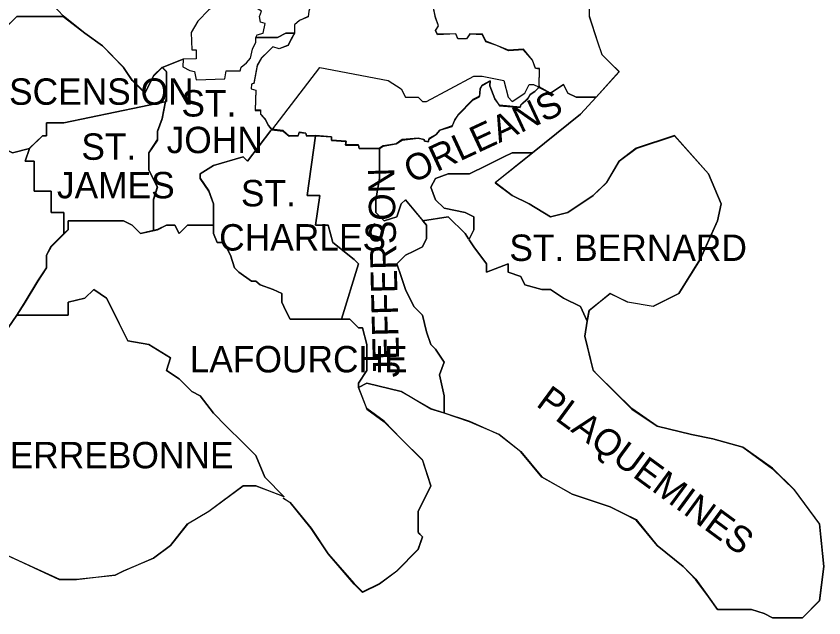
# Model space of a CAD drawing. Extents: x 0.19 to 2.82, y 0.04 to 1.79.
# Drawn here: x 2.4368 to 2.5798, y 1.4148 to 1.5215 of the extents above; entities that cross this region are included whole.
import ezdxf

# ---------------------------------------------------------------- set-up
doc = ezdxf.new("R2010")
doc.units = 0
for name, color, linetype in [('Dist02', 7, 'Continuous'), ('Dist61', 7, 'Continuous'), ('Dist62', 7, 'Continuous'), ('Standard Info', 7, 'Continuous')]:
    doc.layers.add(name, color=color, linetype=linetype)

msp = doc.modelspace()

# ---------------------------------------------------------------- linework, layer by layer
at = {"layer": 'Dist02'}
for points in [[(2.5294, 1.50908), (2.52924, 1.50867), (2.52865, 1.50808), (2.52782, 1.50758), (2.5274, 1.50692), (2.52615, 1.50575), (2.52607, 1.50533), (2.5224, 1.50567), (2.52157, 1.50683), (2.52065, 1.50908), (2.52074, 1.51), (2.51932, 1.50925), (2.51899, 1.50858), (2.51882, 1.50725), (2.51765, 1.50667), (2.51507, 1.504), (2.51449, 1.50308), (2.51399, 1.502), (2.51182, 1.50125), (2.51115, 1.5005), (2.5099, 1.49975), (2.50982, 1.49925), (2.50915, 1.49933), (2.50899, 1.49958), (2.50799, 1.49983), (2.50515, 1.49958), (2.50407, 1.49883), (2.50182, 1.4985), (2.50115, 1.49808)], [(2.53949, 1.50708), (2.53599, 1.50708), (2.53449, 1.50783), (2.53374, 1.50933), (2.5314, 1.50783), (2.5294, 1.50892)], [(2.53674, 1.50408), (2.53949, 1.50708)], [(2.52824, 1.49725), (2.53674, 1.50408)], [(2.4819, 1.50117), (2.47774, 1.49575), (2.47699, 1.4965), (2.47174, 1.495), (2.4694, 1.4935), (2.4694, 1.49275), (2.4709, 1.4905), (2.47174, 1.48817), (2.47174, 1.48442)], [(2.48982, 1.50033), (2.48824, 1.50025), (2.48807, 1.50075), (2.4869, 1.50092), (2.48674, 1.50033), (2.48515, 1.50025), (2.48407, 1.50117), (2.48199, 1.50142)], [(2.50115, 1.49808), (2.49757, 1.498), (2.4974, 1.49867), (2.49515, 1.49867), (2.49524, 1.49933), (2.49265, 1.4995), (2.49265, 1.50008), (2.48982, 1.50033)], [(2.5379, 1.4675), (2.53824, 1.46933), (2.54199, 1.47233), (2.54507, 1.47083), (2.54957, 1.47008), (2.55415, 1.47233), (2.5579, 1.47842), (2.56099, 1.48517), (2.56165, 1.48817), (2.5594, 1.4935), (2.5534, 1.50033), (2.54657, 1.49808), (2.54357, 1.49575), (2.54132, 1.492), (2.53899, 1.48967), (2.53449, 1.48667), (2.5314, 1.48592), (2.52765, 1.48817), (2.52465, 1.48967), (2.52165, 1.492), (2.52824, 1.49725)], [(2.47174, 1.48442), (2.46715, 1.48442), (2.46565, 1.48292), (2.4649, 1.48442), (2.4634, 1.48442), (2.46182, 1.48367), (2.45882, 1.48292), (2.45732, 1.48442), (2.45582, 1.48517), (2.45357, 1.48517), (2.44599, 1.48517), (2.44599, 1.48367), (2.44299, 1.48067), (2.44215, 1.47908), (2.44215, 1.47683), (2.44065, 1.47458), (2.4384, 1.47083), (2.4369, 1.4685)], [(2.4369, 1.4685), (2.4354, 1.46625), (2.43315, 1.4625), (2.43007, 1.461), (2.42932, 1.46025), (2.42707, 1.45875), (2.42482, 1.45942), (2.42332, 1.45875), (2.42182, 1.45725), (2.41874, 1.45417), (2.41724, 1.45192), (2.41799, 1.44967), (2.41799, 1.44817), (2.42032, 1.44508), (2.42182, 1.44358), (2.42182, 1.44208), (2.42099, 1.44133), (2.41949, 1.43983), (2.41799, 1.43825), (2.41574, 1.43492)], [(2.51257, 1.45117), (2.51707, 1.44967), (2.52232, 1.44733), (2.52615, 1.44433), (2.5299, 1.43983), (2.53524, 1.43675), (2.54199, 1.4345), (2.54657, 1.43225), (2.55032, 1.42767), (2.5549, 1.42392), (2.55715, 1.42167), (2.5594, 1.41858), (2.56099, 1.41633), (2.56315, 1.41633), (2.56549, 1.41633), (2.56699, 1.41633), (2.56924, 1.41558), (2.57074, 1.41483), (2.57607, 1.41483), (2.57907, 1.41792), (2.57982, 1.42392), (2.57907, 1.4315), (2.57457, 1.43758), (2.57074, 1.44133), (2.56549, 1.44508), (2.56015, 1.44658), (2.5564, 1.44733), (2.55032, 1.44883), (2.54582, 1.45192), (2.53974, 1.45792), (2.53899, 1.45875), (2.53749, 1.46475), (2.5379, 1.46742)], [(2.4974, 1.45567), (2.4989, 1.45642), (2.50499, 1.45492), (2.51024, 1.45192), (2.51257, 1.45117)], [(2.48407, 1.43608), (2.48532, 1.43525), (2.48907, 1.43075), (2.49207, 1.42617), (2.49665, 1.42092), (2.49815, 1.41942), (2.50115, 1.42092), (2.50424, 1.42317), (2.50799, 1.427), (2.50874, 1.42917), (2.50799, 1.43), (2.50799, 1.43375), (2.51024, 1.43825), (2.50874, 1.44283), (2.50499, 1.44658), (2.50199, 1.44967), (2.4989, 1.45192), (2.4974, 1.45567)], [(2.41574, 1.43492), (2.41799, 1.43225), (2.42782, 1.4285), (2.43465, 1.42617), (2.44449, 1.42167), (2.44749, 1.42167), (2.45432, 1.42242), (2.45582, 1.42317), (2.46115, 1.42542), (2.46415, 1.42767), (2.46715, 1.4315), (2.4709, 1.43375), (2.47699, 1.43825), (2.47924, 1.43825), (2.48424, 1.43633)]]:
    msp.add_lwpolyline(points, dxfattribs=at)
at = {"layer": 'Dist61'}
for points in [[(2.4634, 1.50633), (2.4634, 1.51167), (2.46265, 1.51242), (2.46115, 1.51092), (2.45957, 1.50783), (2.45882, 1.50867), (2.45732, 1.51017), (2.45582, 1.51242), (2.45207, 1.51617), (2.44899, 1.51842), (2.44515, 1.5215)], [(2.46115, 1.48367), (2.46115, 1.48667), (2.46115, 1.489), (2.46182, 1.49125), (2.46032, 1.49425), (2.46032, 1.49575), (2.46032, 1.49725), (2.46182, 1.49958), (2.46182, 1.50108), (2.46265, 1.50333), (2.46324, 1.50642)], [(2.44524, 1.48292), (2.44599, 1.48367), (2.44599, 1.48517), (2.45357, 1.48517), (2.45582, 1.48517), (2.45732, 1.48442), (2.45882, 1.48292), (2.46115, 1.4835)], [(2.4309, 1.46133), (2.43315, 1.4625), (2.4354, 1.46625), (2.4369, 1.4685), (2.4384, 1.47083), (2.44065, 1.47458), (2.44215, 1.47683), (2.44215, 1.47908), (2.44299, 1.48067), (2.44524, 1.48292)]]:
    msp.add_lwpolyline(points, dxfattribs=at)
at = {"layer": 'Dist62'}
for points in [[(2.52174, 1.551), (2.52232, 1.548), (2.5239, 1.54492), (2.52765, 1.53808), (2.53074, 1.53433), (2.53449, 1.53133), (2.53749, 1.52525), (2.53824, 1.523), (2.53824, 1.5215), (2.53974, 1.51692), (2.54049, 1.51467), (2.54199, 1.51317), (2.54357, 1.51167), (2.53949, 1.50708)], [(2.49207, 1.52675), (2.49165, 1.52642), (2.4909, 1.52625), (2.48982, 1.52592), (2.48974, 1.52392), (2.48907, 1.52358), (2.48865, 1.52233), (2.48849, 1.52142), (2.48699, 1.52067), (2.48607, 1.51992), (2.48607, 1.51842)], [(2.5294, 1.50908), (2.52949, 1.51217), (2.52874, 1.51225), (2.52824, 1.51367), (2.52665, 1.51558), (2.52399, 1.51542), (2.5219, 1.51625), (2.51999, 1.517), (2.5194, 1.51825), (2.51715, 1.51833), (2.51657, 1.51742), (2.51499, 1.5175), (2.51465, 1.51833), (2.5114, 1.51825), (2.51107, 1.51892), (2.51157, 1.51975), (2.51107, 1.52125), (2.51065, 1.52325)], [(2.4634, 1.50633), (2.4634, 1.51167), (2.46265, 1.51242), (2.46115, 1.51092), (2.45957, 1.50783), (2.45882, 1.50867), (2.45732, 1.51017), (2.45582, 1.51242), (2.45207, 1.51617), (2.44899, 1.51842), (2.44515, 1.5215)], [(2.48607, 1.51842), (2.48549, 1.51742), (2.48499, 1.51633), (2.4834, 1.51567), (2.48224, 1.516), (2.48149, 1.51525), (2.48024, 1.51408), (2.47949, 1.51275), (2.4789, 1.50958), (2.47849, 1.50942), (2.4784, 1.50858), (2.47924, 1.50833), (2.47915, 1.50483), (2.48007, 1.50483), (2.48007, 1.50417), (2.4809, 1.50325), (2.48149, 1.50208), (2.48199, 1.50142)], [(2.53949, 1.50708), (2.53599, 1.50708), (2.53449, 1.50783), (2.53374, 1.50933), (2.5314, 1.50783), (2.5294, 1.50892)], [(2.46115, 1.48367), (2.46115, 1.48667), (2.46115, 1.489), (2.46182, 1.49125), (2.46032, 1.49425), (2.46032, 1.49575), (2.46032, 1.49725), (2.46182, 1.49958), (2.46182, 1.50108), (2.46265, 1.50333), (2.46324, 1.50642)], [(2.4819, 1.50117), (2.47774, 1.49575), (2.47699, 1.4965), (2.47174, 1.495), (2.4694, 1.4935), (2.4694, 1.49275), (2.4709, 1.4905), (2.47174, 1.48817), (2.47174, 1.48442)], [(2.47174, 1.48442), (2.46715, 1.48442), (2.46565, 1.48292), (2.4649, 1.48442), (2.4634, 1.48442), (2.46182, 1.48367), (2.46115, 1.4835)]]:
    msp.add_lwpolyline(points, dxfattribs=at)
at = {"layer": 'Standard Info'}
for p, q in [((2.4664, 1.51383), (2.46265, 1.51233)), ((2.46265, 1.51233), (2.4664, 1.51383)), ((2.46265, 1.51233), (2.4664, 1.51383)), ((2.50882, 1.48517), (2.50874, 1.48517)), ((2.46115, 1.48358), (2.46115, 1.48342)), ((2.51699, 1.48183), (2.51707, 1.48208)), ((2.4369, 1.4685), (2.4369, 1.4685))]:
    msp.add_line(p, q, dxfattribs=at)
for points in [[(2.44674, 1.55317), (2.44524, 1.55017), (2.44374, 1.54867), (2.44215, 1.54642), (2.43999, 1.54408), (2.4384, 1.54108), (2.43765, 1.53883), (2.43765, 1.535), (2.43765, 1.532), (2.4384, 1.529), (2.43999, 1.526), (2.44299, 1.52375), (2.44524, 1.52142)], [(2.52174, 1.551), (2.52232, 1.54792), (2.5239, 1.54492), (2.52765, 1.53808), (2.53074, 1.53433), (2.53449, 1.53125), (2.53749, 1.52525), (2.53824, 1.52292), (2.53824, 1.52142), (2.53974, 1.51692), (2.54049, 1.51467), (2.54199, 1.51317), (2.54357, 1.51158), (2.53949, 1.50708)], [(2.46265, 1.51233), (2.46115, 1.51083), (2.45957, 1.50783), (2.45882, 1.50858), (2.45732, 1.51008), (2.45582, 1.51233), (2.45207, 1.51617), (2.44899, 1.51842), (2.44524, 1.52142), (2.44299, 1.52375), (2.43999, 1.526), (2.4384, 1.529), (2.43765, 1.532), (2.43765, 1.535), (2.43765, 1.53883), (2.4384, 1.54108), (2.43999, 1.54408), (2.44215, 1.54642), (2.44274, 1.54725)], [(2.49207, 1.52675), (2.49165, 1.52633), (2.4909, 1.52625), (2.48982, 1.52583), (2.48974, 1.52392), (2.48907, 1.5235), (2.48865, 1.52233), (2.48849, 1.52133), (2.48699, 1.52067), (2.48607, 1.51992), (2.48607, 1.51842)], [(2.47924, 1.51767), (2.47949, 1.51817), (2.48057, 1.51842), (2.4809, 1.52017), (2.48007, 1.52042), (2.4799, 1.52142), (2.48024, 1.52233), (2.4789, 1.52317), (2.47757, 1.52342), (2.47649, 1.52408), (2.47649, 1.52525), (2.47432, 1.52525), (2.47324, 1.52442)], [(2.47324, 1.52442), (2.4709, 1.52258), (2.46899, 1.52058), (2.46782, 1.51858), (2.4679, 1.5155), (2.46865, 1.5155), (2.46865, 1.51392), (2.4664, 1.51383), (2.46265, 1.51233)], [(2.5294, 1.509), (2.52949, 1.51208), (2.52874, 1.51217), (2.52824, 1.51367), (2.52665, 1.5155), (2.52399, 1.51533), (2.5219, 1.51625), (2.51999, 1.51692), (2.5194, 1.51817), (2.51715, 1.51825), (2.51657, 1.51742), (2.51499, 1.51742), (2.51465, 1.51833), (2.5114, 1.51817), (2.51107, 1.51883), (2.51157, 1.51975), (2.51107, 1.52117), (2.51065, 1.52317)], [(2.42857, 1.49725), (2.42857, 1.4995), (2.42857, 1.501), (2.43007, 1.50258), (2.43007, 1.50408), (2.4309, 1.50558), (2.43157, 1.51158), (2.4339, 1.51842), (2.4369, 1.52142), (2.44524, 1.52142)], [(2.44524, 1.52142), (2.4369, 1.52142), (2.43465, 1.51917)], [(2.44515, 1.52142), (2.44899, 1.51842), (2.45207, 1.51617), (2.45582, 1.51233), (2.45732, 1.51008), (2.45882, 1.50858), (2.45957, 1.50783), (2.46115, 1.51083), (2.46265, 1.51233), (2.4634, 1.51158), (2.4634, 1.50633)], [(2.4664, 1.51383), (2.46632, 1.5125), (2.46757, 1.51183), (2.4684, 1.51167), (2.46865, 1.51017), (2.47374, 1.51033), (2.47399, 1.51175), (2.47649, 1.51175), (2.47665, 1.51242), (2.47757, 1.51317), (2.47832, 1.514), (2.47865, 1.51558), (2.47924, 1.51683), (2.47924, 1.51767)], [(2.48607, 1.51842), (2.48549, 1.51733), (2.48499, 1.51625), (2.4834, 1.51567), (2.48224, 1.516), (2.48149, 1.51525), (2.48024, 1.514), (2.47949, 1.51267), (2.4789, 1.5095), (2.47849, 1.50942), (2.4784, 1.50858), (2.47924, 1.50833), (2.47915, 1.50475), (2.48007, 1.50475), (2.48007, 1.50408), (2.4809, 1.50317), (2.48149, 1.502), (2.48199, 1.50133)], [(2.48607, 1.51842), (2.48457, 1.51842), (2.48307, 1.51767), (2.47924, 1.51767)], [(2.47924, 1.51767), (2.48307, 1.51767), (2.48457, 1.51842), (2.48607, 1.51842)], [(2.46115, 1.48358), (2.46115, 1.48667), (2.46115, 1.48892), (2.46182, 1.49117), (2.46032, 1.49417), (2.46032, 1.49575), (2.46032, 1.49725), (2.46182, 1.4995), (2.46182, 1.501), (2.46265, 1.50325), (2.4634, 1.50708), (2.4634, 1.51158), (2.46265, 1.51233)], [(2.48207, 1.50125), (2.49057, 1.51233), (2.50265, 1.51008), (2.50499, 1.50858), (2.50574, 1.50708), (2.50799, 1.50708), (2.50874, 1.50633), (2.50949, 1.50633), (2.51782, 1.51083), (2.51932, 1.51083), (2.52315, 1.51008), (2.5239, 1.50708), (2.52465, 1.50633), (2.5269, 1.50783), (2.52765, 1.50933), (2.5284, 1.50933), (2.52932, 1.50892)], [(2.48207, 1.50125), (2.49057, 1.51233), (2.50265, 1.51008), (2.50499, 1.50858), (2.50574, 1.50708), (2.50799, 1.50708), (2.50874, 1.50633), (2.50949, 1.50633), (2.51782, 1.51083), (2.51932, 1.51083), (2.52315, 1.51008), (2.5239, 1.50708), (2.52465, 1.50633), (2.5269, 1.50783), (2.52765, 1.50933), (2.5284, 1.50933), (2.52932, 1.50892)], [(2.50115, 1.498), (2.50182, 1.49842), (2.50407, 1.49883), (2.50515, 1.4995), (2.50799, 1.49983), (2.50899, 1.49958), (2.50915, 1.49933), (2.50982, 1.49917), (2.5099, 1.49967), (2.51115, 1.5005), (2.51182, 1.50125), (2.51399, 1.50192), (2.51449, 1.50308), (2.51507, 1.50392), (2.51765, 1.50658), (2.51882, 1.50717), (2.51899, 1.50858), (2.51932, 1.50917), (2.52074, 1.51), (2.52065, 1.50908), (2.52157, 1.50683), (2.5224, 1.50558), (2.52607, 1.50525), (2.52615, 1.50575), (2.5274, 1.50683), (2.52782, 1.50758), (2.52865, 1.50808), (2.52924, 1.50867), (2.5294, 1.509)], [(2.5294, 1.50883), (2.5314, 1.50783), (2.53374, 1.50933), (2.53449, 1.50783), (2.53599, 1.50708), (2.53949, 1.50708)], [(2.53899, 1.50708), (2.53599, 1.50708), (2.53449, 1.50783), (2.53374, 1.50933), (2.5314, 1.50783), (2.5294, 1.50883)], [(2.4634, 1.50633), (2.44524, 1.50258), (2.44215, 1.50258), (2.44215, 1.50025), (2.44149, 1.50025), (2.43915, 1.498), (2.43615, 1.49725), (2.43465, 1.498), (2.4339, 1.498), (2.4324, 1.498), (2.4309, 1.498), (2.43007, 1.49875), (2.42857, 1.49725)], [(2.43915, 1.49808), (2.44149, 1.50025), (2.44215, 1.50025), (2.44215, 1.50258), (2.44524, 1.50258), (2.4634, 1.50633)], [(2.46324, 1.50633), (2.46265, 1.50325), (2.46182, 1.501), (2.46182, 1.4995), (2.46032, 1.49725), (2.46032, 1.49575), (2.46032, 1.49417), (2.46182, 1.49117), (2.46115, 1.48892), (2.46115, 1.48667), (2.46115, 1.48358)], [(2.53949, 1.50708), (2.53674, 1.50408)], [(2.53674, 1.50408), (2.52824, 1.49725)], [(2.4819, 1.50117), (2.47774, 1.49575), (2.47699, 1.4965), (2.47174, 1.495), (2.4694, 1.4935), (2.4694, 1.49267), (2.4709, 1.49042), (2.47174, 1.48817), (2.47174, 1.48442)], [(2.47174, 1.48442), (2.47174, 1.48817), (2.4709, 1.49042), (2.4694, 1.49267), (2.4694, 1.4935), (2.47174, 1.495), (2.47699, 1.4965), (2.47774, 1.49575), (2.4819, 1.50117)], [(2.48199, 1.50133), (2.48407, 1.50108), (2.48515, 1.50017), (2.48674, 1.50025), (2.4869, 1.50083), (2.48807, 1.50075), (2.48824, 1.50017), (2.48982, 1.50025)], [(2.48982, 1.50025), (2.48832, 1.48967), (2.49057, 1.48967), (2.48982, 1.48442), (2.49207, 1.48442), (2.4929, 1.48133), (2.49665, 1.47833), (2.4974, 1.47758), (2.4944, 1.46775)], [(2.4944, 1.46775), (2.4974, 1.47758), (2.49665, 1.47833), (2.4929, 1.48133), (2.49207, 1.48442), (2.48982, 1.48442), (2.49057, 1.48967), (2.48832, 1.48967), (2.48982, 1.50025)], [(2.48982, 1.50025), (2.49265, 1.50008), (2.49265, 1.49942), (2.49524, 1.49925), (2.49515, 1.49858), (2.4974, 1.49858), (2.49757, 1.498), (2.50115, 1.498)], [(2.52824, 1.49725), (2.52165, 1.49192), (2.52465, 1.48967), (2.52765, 1.48817), (2.5314, 1.48592), (2.53449, 1.48667), (2.53899, 1.48967), (2.54132, 1.49192), (2.54357, 1.49575), (2.54657, 1.498), (2.5534, 1.50025), (2.5594, 1.4935), (2.56165, 1.48817), (2.56099, 1.48517), (2.5579, 1.47833), (2.55415, 1.47233), (2.54957, 1.47), (2.54507, 1.47075), (2.54199, 1.47233), (2.53824, 1.46925), (2.5379, 1.46742)], [(2.42857, 1.49725), (2.43007, 1.49875), (2.4309, 1.498), (2.4324, 1.498), (2.4339, 1.498), (2.43465, 1.498), (2.43615, 1.49725), (2.43915, 1.498)], [(2.43915, 1.498), (2.4384, 1.49575), (2.43999, 1.49575), (2.43999, 1.49042), (2.44299, 1.49042), (2.44299, 1.48667), (2.44524, 1.48667), (2.44524, 1.48292)], [(2.44524, 1.48292), (2.44524, 1.48667), (2.44299, 1.48667), (2.44299, 1.49042), (2.43999, 1.49042), (2.43999, 1.49575), (2.4384, 1.49575), (2.43915, 1.498)], [(2.50115, 1.498), (2.50115, 1.49267), (2.50049, 1.48892), (2.50049, 1.48667), (2.50199, 1.48517), (2.50424, 1.48592), (2.50499, 1.48817), (2.50574, 1.48892), (2.50949, 1.48442), (2.50949, 1.48208), (2.50874, 1.48058), (2.50724, 1.47983), (2.50574, 1.47908), (2.50424, 1.47758), (2.50499, 1.47533), (2.50574, 1.473), (2.50724, 1.47), (2.50874, 1.4685), (2.50949, 1.4655), (2.51024, 1.46325), (2.51107, 1.46242), (2.51257, 1.46017), (2.51174, 1.45792), (2.51257, 1.45417), (2.51257, 1.45108)], [(2.5089, 1.48517), (2.50574, 1.48892), (2.50499, 1.48817), (2.50424, 1.48592), (2.50199, 1.48517), (2.50049, 1.48667), (2.50049, 1.48892), (2.50115, 1.49267), (2.50115, 1.498)], [(2.52824, 1.49725), (2.52615, 1.49725), (2.52465, 1.49725), (2.52315, 1.4965), (2.52007, 1.495), (2.51707, 1.4935), (2.51332, 1.4935), (2.51107, 1.49267), (2.51024, 1.49117), (2.51107, 1.48892), (2.51257, 1.48742), (2.51632, 1.48667), (2.51782, 1.48592), (2.51782, 1.48358), (2.51707, 1.48208)], [(2.51707, 1.48208), (2.51782, 1.48358), (2.51782, 1.48592), (2.51632, 1.48667), (2.51257, 1.48742), (2.51107, 1.48892), (2.51024, 1.49117), (2.51107, 1.49267), (2.51332, 1.4935), (2.51707, 1.4935), (2.52007, 1.495), (2.52315, 1.4965), (2.52465, 1.49725), (2.52615, 1.49725), (2.52824, 1.49725)], [(2.4369, 1.4685), (2.4384, 1.47075), (2.44065, 1.4745), (2.44215, 1.47683), (2.44215, 1.47908), (2.44299, 1.48058), (2.44599, 1.48358), (2.44599, 1.48517), (2.45357, 1.48517), (2.45582, 1.48517), (2.45732, 1.48442), (2.45882, 1.48292), (2.46182, 1.48358), (2.4634, 1.48442), (2.4649, 1.48442), (2.46565, 1.48292), (2.46715, 1.48442), (2.47174, 1.48442)], [(2.46115, 1.48342), (2.45882, 1.48292), (2.45732, 1.48442), (2.45582, 1.48517), (2.45357, 1.48517), (2.44599, 1.48517), (2.44599, 1.48358), (2.44524, 1.48283)], [(2.51257, 1.45108), (2.51257, 1.45417), (2.51174, 1.45792), (2.51257, 1.46017), (2.51107, 1.46242), (2.51024, 1.46325), (2.50949, 1.4655), (2.50874, 1.4685), (2.50724, 1.47), (2.50574, 1.473), (2.50499, 1.47533), (2.50424, 1.47758), (2.50574, 1.47908), (2.50724, 1.47983), (2.50874, 1.48058), (2.50949, 1.48208), (2.50949, 1.48442), (2.50882, 1.48517)], [(2.5169, 1.482), (2.51632, 1.48292), (2.51332, 1.48592), (2.50874, 1.48517)], [(2.50874, 1.48517), (2.51332, 1.48592), (2.51632, 1.48292), (2.5169, 1.482)], [(2.47174, 1.48442), (2.46715, 1.48442), (2.46565, 1.48292), (2.4649, 1.48442), (2.4634, 1.48442), (2.46182, 1.48358), (2.46115, 1.48342)], [(2.47174, 1.48442), (2.47174, 1.48292), (2.4724, 1.48133), (2.47324, 1.48133), (2.47399, 1.48058), (2.47474, 1.47908), (2.47549, 1.47683), (2.47624, 1.47608), (2.47849, 1.4745), (2.47924, 1.4745), (2.47999, 1.47383), (2.48232, 1.473), (2.48382, 1.47233), (2.48382, 1.47075), (2.48457, 1.46925), (2.48532, 1.46775), (2.4959, 1.46775), (2.4974, 1.46625), (2.49815, 1.46625), (2.4989, 1.46325), (2.4989, 1.46092), (2.4989, 1.45867), (2.4974, 1.45642), (2.4974, 1.45567)], [(2.4944, 1.46775), (2.48532, 1.46775), (2.48457, 1.46925), (2.48382, 1.47075), (2.48382, 1.47233), (2.48232, 1.473), (2.47999, 1.47383), (2.47924, 1.4745), (2.47849, 1.4745), (2.47624, 1.47608), (2.47549, 1.47683), (2.47474, 1.47908), (2.47399, 1.48058), (2.47324, 1.48133), (2.4724, 1.48133), (2.47174, 1.48292), (2.47174, 1.48442)], [(2.44524, 1.48283), (2.44299, 1.48058), (2.44215, 1.47908), (2.44215, 1.47683), (2.44065, 1.4745), (2.4384, 1.47075), (2.4369, 1.4685), (2.4354, 1.46625), (2.43315, 1.46242), (2.4309, 1.46133)], [(2.5379, 1.46742), (2.53674, 1.47), (2.53374, 1.4715), (2.5314, 1.473), (2.5299, 1.473), (2.5269, 1.47383), (2.52615, 1.47533), (2.5239, 1.47608), (2.5239, 1.47758), (2.52007, 1.47608), (2.52007, 1.47758), (2.51782, 1.48058), (2.51699, 1.48183)], [(2.51699, 1.48183), (2.51782, 1.48058), (2.52007, 1.47758), (2.52007, 1.47608), (2.5239, 1.47758), (2.5239, 1.47608), (2.52615, 1.47533), (2.5269, 1.47383), (2.5299, 1.473), (2.5314, 1.473), (2.53374, 1.4715), (2.53674, 1.47), (2.5379, 1.46742)], [(2.4369, 1.4685), (2.44599, 1.4685), (2.44599, 1.47075), (2.44899, 1.4715), (2.45057, 1.473), (2.45282, 1.4715), (2.45357, 1.47), (2.45507, 1.467), (2.45657, 1.46392), (2.46032, 1.46325), (2.46415, 1.46092), (2.4634, 1.45867), (2.46565, 1.45717), (2.4679, 1.45492), (2.4694, 1.45417), (2.47174, 1.45108), (2.47399, 1.44883), (2.47699, 1.44583), (2.47924, 1.44358), (2.48082, 1.43975), (2.48424, 1.43625)], [(2.48424, 1.43625), (2.48082, 1.43975), (2.47924, 1.44358), (2.47699, 1.44583), (2.47399, 1.44883), (2.47174, 1.45108), (2.4694, 1.45417), (2.4679, 1.45492), (2.46565, 1.45717), (2.4634, 1.45867), (2.46415, 1.46092), (2.46032, 1.46325), (2.45657, 1.46392), (2.45507, 1.467), (2.45357, 1.47), (2.45282, 1.4715), (2.45057, 1.473), (2.44899, 1.4715), (2.44599, 1.47075), (2.44599, 1.4685), (2.4369, 1.4685)], [(2.41574, 1.43492), (2.41799, 1.43825), (2.41949, 1.43975), (2.42099, 1.44125), (2.42182, 1.44208), (2.42182, 1.44358), (2.42032, 1.44508), (2.41799, 1.44808), (2.41799, 1.44958), (2.41724, 1.45183), (2.41874, 1.45417), (2.42182, 1.45717), (2.42332, 1.45867), (2.42482, 1.45942), (2.42707, 1.45867), (2.42932, 1.46017), (2.43007, 1.46092), (2.43315, 1.46242), (2.4354, 1.46625), (2.4369, 1.4685)], [(2.4974, 1.45567), (2.4974, 1.45642), (2.4989, 1.45867), (2.4989, 1.46092), (2.4989, 1.46325), (2.49815, 1.46625), (2.4974, 1.46625), (2.4959, 1.46775), (2.4944, 1.46775)], [(2.5379, 1.46742), (2.53749, 1.46475), (2.53899, 1.45867), (2.53974, 1.45792), (2.54582, 1.45183), (2.55032, 1.44883), (2.5564, 1.44733), (2.56015, 1.44658), (2.56549, 1.44508), (2.57074, 1.44125), (2.57457, 1.4375), (2.57907, 1.43142), (2.57982, 1.42392), (2.57907, 1.41783), (2.57607, 1.41483), (2.57074, 1.41483), (2.56924, 1.41558), (2.56699, 1.41633), (2.56549, 1.41633), (2.56315, 1.41633), (2.56099, 1.41633), (2.5594, 1.41858), (2.55715, 1.42158), (2.5549, 1.42392), (2.55032, 1.42767), (2.54657, 1.43217), (2.54199, 1.4345), (2.53524, 1.43675), (2.5299, 1.43975), (2.52615, 1.44425), (2.52232, 1.44733), (2.51707, 1.44958), (2.51257, 1.45108)], [(2.51257, 1.45108), (2.51024, 1.45183), (2.50499, 1.45492), (2.4989, 1.45642), (2.4974, 1.45567)], [(2.4974, 1.45567), (2.4989, 1.45183), (2.50199, 1.44958), (2.50499, 1.44658), (2.50874, 1.44275), (2.51024, 1.43825), (2.50799, 1.43367), (2.50799, 1.42992), (2.50874, 1.42917), (2.50799, 1.42692), (2.50424, 1.42308), (2.50115, 1.42083), (2.49815, 1.41933), (2.49665, 1.42083), (2.49207, 1.42617), (2.48907, 1.43067), (2.48532, 1.43525), (2.48407, 1.436)], [(2.48424, 1.43625), (2.47924, 1.43825), (2.47699, 1.43825), (2.4709, 1.43367), (2.46715, 1.43142), (2.46415, 1.42767), (2.46115, 1.42542), (2.45582, 1.42308), (2.45432, 1.42242), (2.44749, 1.42158), (2.44449, 1.42158), (2.43465, 1.42617), (2.42782, 1.42842), (2.41799, 1.43217), (2.41574, 1.43492)]]:
    msp.add_lwpolyline(points, dxfattribs=at)

# ---------------------------------------------------------------- texts
for s, p in [('ASCENSION', (2.43137, 1.50575)), ('ST.', (2.46607, 1.50367)), ('JOHN', (2.46345, 1.49718)), ('ST.', (2.44835, 1.496)), ('JAMES', (2.44402, 1.48917)), ('ST.', (2.4766, 1.48775)), ('CHARLES', (2.47275, 1.47992)), ('ST. BERNARD', (2.52414, 1.47808)), ('LAFOURCHE', (2.46753, 1.45833)), ('TERREBONNE', (2.43184, 1.44133))]:
    msp.add_text(s, height=0.004679, dxfattribs=at).set_placement(p)
for s, height, rotation, p in [('ORLEANS', 0.004678, 24.9246, (2.50686, 1.49175)), ('JEFFERSON', 0.004679, 91.4837, (2.50471, 1.45746)), ('PLAQUEMINES', 0.004679, 323.7253, (2.52868, 1.45249))]:
    msp.add_text(s, height=height, rotation=rotation, dxfattribs=at).set_placement(p)

doc.saveas('drawing.dxf')
